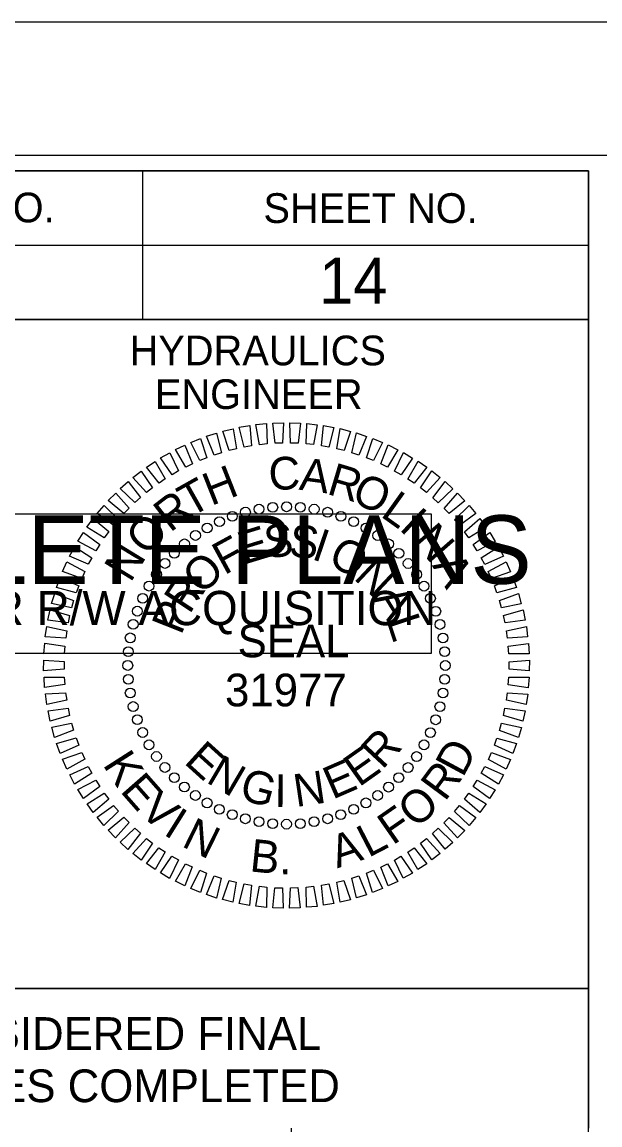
# Model space of a CAD drawing. Extents: x 557032 to 558930, y 525869 to 527437.
# Drawn here: x 558604.2 to 558701.3, y 526783.7 to 526969.2 of the extents above; entities that cross this region are included whole.
import ezdxf

# ---------------------------------------------------------------- set-up
doc = ezdxf.new("R2010")
doc.units = 0
for name, color, linetype in [('Default', 7, 'Continuous'), ('Sheet Cutting Line CELL', 7, 'Continuous'), ('Sheet Data Field CELL', 7, 'Continuous'), ('Sheet Plot Border Inside CELL', 7, 'Continuous'), ('Sheet Plot Border Outside CELL', 7, 'Continuous'), ('Sheet Profile CELL', 7, 'Continuous'), ('Sheet Profile Grid Major CELL', 7, 'Continuous'), ('Sheet Sticker Exception Certification CELL', 7, 'Continuous'), ('Sheet Sticker Incomplete CELL', 7, 'Continuous')]:
    doc.layers.add(name, color=color, linetype=linetype)

msp = doc.modelspace()

# ---------------------------------------------------------------- linework, layer by layer
at = {"layer": 'Default'}
for points in [[(558639, 526897.14), (558637.92, 526900.4), (558639.66, 526900.8), (558640.22, 526897.45)], [(558641.55, 526897.73), (558640.7, 526901.05), (558642.46, 526901.33), (558642.79, 526897.95)], [(558644.13, 526898.13), (558643.51, 526901.51), (558645.29, 526901.67), (558645.38, 526898.27)], [(558646.73, 526898.36), (558646.35, 526901.77), (558648.13, 526901.8), (558647.99, 526898.41)], [(558649.34, 526898.4), (558649.2, 526901.83), (558650.98, 526901.74), (558650.6, 526898.37)], [(558651.95, 526898.26), (558652.05, 526901.7), (558653.82, 526901.48), (558653.2, 526898.14)], [(558654.54, 526897.94), (558654.88, 526901.36), (558656.63, 526901.02), (558655.78, 526897.73)], [(558657.11, 526897.44), (558657.68, 526900.83), (558659.4, 526900.37), (558658.33, 526897.14)], [(558634.07, 526895.45), (558632.54, 526898.52), (558634.2, 526899.16), (558635.23, 526895.92)], [(558636.51, 526896.38), (558635.2, 526899.56), (558636.9, 526900.08), (558637.7, 526896.78)], [(558659.63, 526896.76), (558660.44, 526900.1), (558662.12, 526899.52), (558660.83, 526896.38)], [(558662.1, 526895.91), (558663.14, 526899.18), (558664.78, 526898.49), (558663.27, 526895.45)], [(558629.41, 526893.08), (558627.47, 526895.92), (558629.03, 526896.78), (558630.5, 526893.72)], [(558631.7, 526894.34), (558629.96, 526897.31), (558631.58, 526898.06), (558632.83, 526894.9)], [(558664.5, 526894.89), (558665.77, 526898.08), (558667.35, 526897.27), (558665.63, 526894.34)], [(558666.83, 526893.7), (558668.31, 526896.8), (558669.84, 526895.88), (558667.92, 526893.08)], [(558627.22, 526891.66), (558625.09, 526894.35), (558626.58, 526895.32), (558628.26, 526892.37)], [(558669.06, 526892.35), (558670.76, 526895.34), (558672.22, 526894.32), (558670.11, 526891.66)], [(558625.13, 526890.09), (558622.82, 526892.63), (558624.24, 526893.7), (558626.12, 526890.87)], [(558671.2, 526890.85), (558673.11, 526893.71), (558674.49, 526892.59), (558672.2, 526890.08)], [(558623.16, 526888.38), (558620.68, 526890.75), (558622.02, 526891.92), (558624.09, 526889.22)], [(558673.23, 526889.21), (558675.33, 526891.93), (558676.63, 526890.71), (558674.17, 526888.37)], [(558621.31, 526886.53), (558618.67, 526888.72), (558619.93, 526889.98), (558622.18, 526887.44)], [(558675.14, 526887.42), (558677.42, 526889.99), (558678.64, 526888.69), (558676.02, 526886.53)], [(558619.6, 526884.56), (558616.81, 526886.57), (558617.97, 526887.91), (558620.4, 526885.53)], [(558676.92, 526885.51), (558679.38, 526887.91), (558680.5, 526886.53), (558677.73, 526884.55)], [(558618.02, 526882.48), (558615.1, 526884.28), (558616.17, 526885.7), (558618.76, 526883.5)], [(558678.56, 526883.48), (558681.18, 526885.71), (558682.2, 526884.25), (558679.31, 526882.47)], [(558616.6, 526880.29), (558613.56, 526881.88), (558614.53, 526883.37), (558617.26, 526881.36)], [(558680.06, 526881.34), (558682.83, 526883.38), (558683.74, 526881.85), (558680.73, 526880.28)], [(558615.33, 526878.01), (558612.18, 526879.38), (558613.05, 526880.94), (558615.91, 526879.12)], [(558681.4, 526879.1), (558684.3, 526880.94), (558685.11, 526879.35), (558682, 526877.99)], [(558614.23, 526875.64), (558610.99, 526876.79), (558611.74, 526878.41), (558614.73, 526876.79)], [(558682.58, 526876.77), (558685.61, 526878.4), (558686.3, 526876.76), (558683.1, 526875.63)], [(558613.29, 526873.2), (558609.98, 526874.13), (558610.62, 526875.79), (558613.71, 526874.39)], [(558683.6, 526874.37), (558686.73, 526875.78), (558687.31, 526874.1), (558684.04, 526873.19)], [(558612.52, 526870.7), (558609.16, 526871.4), (558609.68, 526873.1), (558612.86, 526871.92)], [(558684.45, 526871.9), (558687.67, 526873.09), (558688.13, 526871.37), (558684.81, 526870.69)], [(558611.93, 526868.16), (558608.53, 526868.62), (558608.93, 526870.35), (558612.19, 526869.39)], [(558685.13, 526869.37), (558688.42, 526870.34), (558688.76, 526868.59), (558685.39, 526868.15)], [(558611.52, 526865.58), (558608.09, 526865.8), (558608.37, 526867.56), (558611.69, 526866.83)], [(558685.62, 526866.81), (558688.98, 526867.54), (558689.19, 526865.78), (558685.8, 526865.56)], [(558611.29, 526862.98), (558607.86, 526862.96), (558608.01, 526864.73), (558611.37, 526864.23)], [(558685.94, 526864.22), (558689.34, 526864.71), (558689.43, 526862.94), (558686.03, 526862.96)], [(558611.24, 526860.37), (558607.82, 526860.11), (558607.85, 526861.89), (558611.24, 526861.63)], [(558686.07, 526861.61), (558689.5, 526861.87), (558689.47, 526860.09), (558686.08, 526860.35)], [(558611.38, 526857.76), (558607.98, 526857.26), (558607.89, 526859.04), (558611.28, 526859.01)], [(558686.02, 526859), (558689.46, 526859.02), (558689.3, 526857.24), (558685.94, 526857.74)], [(558611.69, 526855.17), (558608.34, 526854.43), (558608.12, 526856.2), (558611.51, 526856.41)], [(558685.79, 526856.4), (558689.22, 526856.18), (558688.94, 526854.42), (558685.63, 526855.15)], [(558612.19, 526852.6), (558608.89, 526851.64), (558608.55, 526853.38), (558611.92, 526853.83)], [(558685.38, 526853.82), (558688.79, 526853.36), (558688.39, 526851.62), (558685.13, 526852.58)], [(558612.86, 526850.08), (558609.64, 526848.88), (558609.18, 526850.6), (558612.51, 526851.29)], [(558684.79, 526851.27), (558688.16, 526850.58), (558687.64, 526848.88), (558684.45, 526850.06)], [(558613.71, 526847.61), (558610.58, 526846.19), (558610, 526847.88), (558613.27, 526848.79)], [(558684.03, 526848.77), (558687.34, 526847.85), (558686.7, 526846.19), (558683.6, 526847.59)], [(558614.73, 526845.2), (558611.71, 526843.57), (558611.01, 526845.21), (558614.21, 526846.35)], [(558683.09, 526846.34), (558686.32, 526845.18), (558685.57, 526843.57), (558682.59, 526845.18)], [(558615.91, 526842.88), (558613.01, 526841.04), (558612.2, 526842.62), (558615.32, 526843.98)], [(558681.98, 526843.97), (558685.13, 526842.59), (558684.27, 526841.04), (558681.4, 526842.86)], [(558617.26, 526840.64), (558614.49, 526838.6), (558613.57, 526840.13), (558616.58, 526841.7)], [(558680.72, 526841.69), (558683.76, 526840.09), (558682.79, 526838.6), (558680.06, 526840.62)], [(558618.75, 526838.49), (558616.13, 526836.27), (558615.11, 526837.73), (558618.01, 526839.51)], [(558679.29, 526839.5), (558682.22, 526837.69), (558681.14, 526836.27), (558678.56, 526838.48)], [(558620.39, 526836.46), (558617.94, 526834.06), (558616.82, 526835.45), (558619.58, 526837.42)], [(558677.72, 526837.41), (558680.51, 526835.41), (558679.34, 526834.07), (558676.91, 526836.45)], [(558622.17, 526834.55), (558619.89, 526831.98), (558618.68, 526833.29), (558621.3, 526835.45)], [(558676, 526835.44), (558678.65, 526833.25), (558677.39, 526831.99), (558675.13, 526834.53)], [(558624.08, 526832.77), (558621.98, 526830.05), (558620.68, 526831.26), (558623.14, 526833.6)], [(558674.15, 526833.6), (558676.64, 526831.23), (558675.3, 526830.06), (558673.22, 526832.75)], [(558626.11, 526831.12), (558624.21, 526828.26), (558622.83, 526829.38), (558625.12, 526831.89)], [(558672.18, 526831.89), (558674.49, 526829.35), (558673.07, 526828.28), (558671.19, 526831.11)], [(558628.25, 526829.62), (558626.55, 526826.64), (558625.09, 526827.66), (558627.2, 526830.32)], [(558670.09, 526830.32), (558672.22, 526827.62), (558670.73, 526826.65), (558669.06, 526829.61)], [(558630.49, 526828.28), (558629, 526825.18), (558627.48, 526826.1), (558629.39, 526828.9)], [(558667.9, 526828.9), (558669.84, 526826.06), (558668.28, 526825.2), (558666.82, 526828.26)], [(558632.81, 526827.09), (558631.55, 526823.9), (558629.96, 526824.7), (558631.68, 526827.63)], [(558635.22, 526826.07), (558634.17, 526822.79), (558632.54, 526823.49), (558634.05, 526826.53)], [(558663.25, 526826.53), (558664.77, 526823.45), (558663.11, 526822.81), (558662.09, 526826.05)], [(558665.62, 526827.63), (558667.35, 526824.67), (558665.74, 526823.92), (558664.49, 526827.07)], [(558637.69, 526825.21), (558636.87, 526821.87), (558635.19, 526822.45), (558636.49, 526825.59)], [(558640.21, 526824.53), (558639.63, 526821.15), (558637.91, 526821.61), (558638.99, 526824.83)], [(558642.77, 526824.03), (558642.43, 526820.62), (558640.69, 526820.96), (558641.53, 526824.24)], [(558655.77, 526824.25), (558656.62, 526820.92), (558654.86, 526820.64), (558654.53, 526824.02)], [(558658.31, 526824.83), (558659.39, 526821.57), (558657.66, 526821.17), (558657.09, 526824.52)], [(558660.81, 526825.6), (558662.11, 526822.42), (558660.41, 526821.9), (558659.62, 526825.2)], [(558645.36, 526823.71), (558645.26, 526820.28), (558643.5, 526820.5), (558644.11, 526823.84)], [(558647.97, 526823.57), (558648.11, 526820.14), (558646.34, 526820.24), (558646.71, 526823.61)], [(558650.58, 526823.62), (558650.96, 526820.2), (558649.18, 526820.17), (558649.33, 526823.57)], [(558653.19, 526823.84), (558653.8, 526820.46), (558652.03, 526820.31), (558651.94, 526823.7)]]:
    msp.add_lwpolyline(points, close=True, dxfattribs=at)
for centre in [(558641.75, 526886.78), (558644.03, 526887.28), (558646.34, 526887.58), (558648.66, 526887.68), (558650.99, 526887.58), (558653.3, 526887.28), (558655.57, 526886.77), (558637.38, 526885.19), (558639.53, 526886.08), (558657.79, 526886.07), (558659.94, 526885.18), (558633.35, 526882.86), (558635.31, 526884.11), (558662.01, 526884.1), (558663.97, 526882.85), (558631.5, 526881.44), (558665.82, 526881.44), (558629.78, 526879.87), (558667.54, 526879.86), (558628.21, 526878.15), (558669.11, 526878.14), (558626.79, 526876.3), (558670.53, 526876.3), (558625.54, 526874.34), (558671.78, 526874.33), (558624.46, 526872.27), (558672.85, 526872.27), (558623.57, 526870.12), (558673.75, 526870.11), (558622.87, 526867.9), (558674.45, 526867.89), (558622.37, 526865.63), (558674.95, 526865.62), (558622.06, 526863.32), (558675.25, 526863.31), (558621.96, 526860.99), (558675.35, 526860.98), (558622.06, 526858.67), (558675.25, 526858.66), (558622.37, 526856.36), (558674.95, 526856.35), (558622.87, 526854.08), (558674.44, 526854.07), (558623.57, 526851.86), (558673.74, 526851.85), (558624.46, 526849.71), (558672.85, 526849.7), (558625.54, 526847.64), (558671.77, 526847.64), (558626.79, 526845.68), (558670.52, 526845.67), (558628.2, 526843.83), (558669.1, 526843.82), (558629.78, 526842.11), (558667.53, 526842.11), (558631.49, 526840.54), (558665.81, 526840.53), (558633.34, 526839.12), (558663.97, 526839.12), (558635.3, 526837.87), (558637.37, 526836.8), (558659.93, 526836.79), (558662, 526837.87), (558639.52, 526835.9), (558641.74, 526835.2), (558644.02, 526834.7), (558653.29, 526834.7), (558655.56, 526835.2), (558657.78, 526835.9), (558646.33, 526834.39), (558648.65, 526834.29), (558650.98, 526834.39)]:
    msp.add_circle(centre, 0.826, dxfattribs=at)
at = {"layer": 'Sheet Cutting Line CELL'}
msp.add_line((558716.45, 526969.22), (557032.45, 526969.22), dxfattribs=at)
at = {"layer": 'Sheet Plot Border Inside CELL'}
msp.add_lwpolyline([(557045.45, 525891.67), (558711.95, 525891.67), (558711.95, 526946.77), (557045.45, 526946.77)], close=True, dxfattribs=at)
at = {"layer": 'Sheet Plot Border Outside CELL'}
msp.add_lwpolyline([(557032.45, 525869.22), (558716.45, 525869.22), (558716.45, 526969.22), (557032.45, 526969.22)], close=True, dxfattribs=at)
at = {"layer": 'Sheet Profile CELL'}
for p, q in [((558624.45, 526944.17), (558624.45, 526919.17)), ((558499.4, 526931.67), (558699.45, 526931.67))]:
    msp.add_line(p, q, dxfattribs=at)
for points in [[(558699.45, 526944.22), (557199.45, 526944.22), (557199.45, 525894.22), (558699.45, 525894.22)], [(558499.4, 526944.22), (558699.45, 526944.22), (558699.45, 526919.17), (558499.4, 526919.17)], [(558599.45, 526919.17), (558699.45, 526919.17), (558699.45, 526806.67), (558599.45, 526806.67)]]:
    msp.add_lwpolyline(points, close=True, dxfattribs=at)
at = {"layer": 'Sheet Profile Grid Major CELL'}
msp.add_lwpolyline([(558649.45, 526783.17), (558649.45, 526444.22), (558699.45, 526444.22), (558699.45, 526794.22)], dxfattribs=at)
at = {"layer": 'Sheet Sticker Exception Certification CELL'}
for p, q in [((558499.4, 526806.67), (558699.44, 526806.67)), ((558499.4, 526806.67), (558699.44, 526806.67)), ((558699.44, 526806.66), (558699.44, 526783.16)), ((558699.44, 526806.66), (558699.44, 526783.16))]:
    msp.add_line(p, q, dxfattribs=at)
at = {"layer": 'Sheet Sticker Incomplete CELL'}
msp.add_lwpolyline([(558525.97, 526863.02), (558525.97, 526886.52), (558672.97, 526886.52), (558672.97, 526863.02)], close=True, dxfattribs=at)

# ---------------------------------------------------------------- texts
at = {"layer": 'Default'}
for s, height, rotation, p in [('C', 5.5, 1.9509, (558645.72, 526890.49)), ('A', 5.5, 352.4458, (558650.64, 526890.57)), ('R', 5.5, 343.3983, (558655.26, 526889.89)), ('H', 5.5, 21.5901, (558635.98, 526887.79)), ('O', 5.5, 335.1897, (558659.32, 526888.65)), ('T', 5.5, 29.3793, (558632.46, 526885.82)), ('R', 5.5, 37.5879, (558629.08, 526883.26)), ('L', 5.5, 324.4645, (558664.29, 526886.18)), ('I', 5.5, 316.9994, (558667.43, 526883.94)), ('O', 5.5, 48.3131, (558625.28, 526879.23)), ('E', 5.5, 16.975, (558641.47, 526877.93)), ('S', 5.5, 5.2127, (558645.08, 526879.04)), ('S', 5.5, 353.2538, (558648.89, 526879.39)), ('I', 5.5, 341.2948, (558652.7, 526878.94)), ('N', 5.5, 311.0594, (558669.7, 526881.87)), ('F', 5.5, 28.6529, (558638.19, 526876.12)), ('O', 5.5, 332.5394, (558655.39, 526878.12)), ('N', 5.5, 58.5235, (558622.42, 526874.79)), ('O', 5.5, 44.4617, (558634.46, 526872.7)), ('N', 5.5, 316.7306, (558659.8, 526875.63)), ('A', 5.5, 300.849, (558673.07, 526877.81)), ('R', 5.5, 56.5612, (558632.32, 526869.47)), ('A', 5.5, 301.6806, (558663.22, 526872.24)), ('P', 5.5, 68.3234, (558630.94, 526865.96)), ('L', 5.5, 288.3447, (558665.42, 526868.58)), ('SEAL', 5.504, 359.989, (558640.43, 526862.37)), ('31977', 5.504, 359.989, (558638.31, 526854.11)), ('R', 5.5, 47.032, (558664.76, 526843.35)), ('K', 5.5, 302.6028, (558617.66, 526844.33)), ('E', 5.5, 317.8396, (558631.25, 526844.63)), ('E', 5.5, 35.2697, (558660.83, 526840.44)), ('D', 5.5, 61.6895, (558678.29, 526842)), ('N', 5.5, 329.6019, (558634.95, 526841.43)), ('E', 5.5, 23.5075, (558656.39, 526838.39)), ('E', 5.5, 311.3071, (558620.54, 526839.83)), ('G', 5.5, 344.6519, (558640.5, 526838.54)), ('N', 5.5, 8.4574, (558650.25, 526837.16)), ('R', 5.5, 53.4809, (558675.27, 526837.96)), ('I', 5.5, 359.702, (558646.61, 526837.19)), ('V', 5.5, 319.287, (558623.75, 526836.13)), ('O', 5.5, 42.7557, (558670.52, 526833.41)), ('F', 5.5, 34.833, (558666.51, 526830.66)), ('I', 5.5, 327.9723, (558627.79, 526832.65)), ('N', 5.5, 333.9122, (558630.83, 526830.64)), ('L', 5.5, 27.3679, (558662.42, 526828.6)), ('B', 5.5, 354.009, (558642.34, 526826.37)), ('A', 5.5, 18.3204, (558657.16, 526826.84)), ('.', 5.5, 2.3511, (558647.43, 526825.82))]:
    msp.add_text(s, height=height, rotation=rotation, dxfattribs=at).set_placement(p)
at = {"layer": 'Sheet Data Field CELL'}
msp.add_text('14 ', height=7.75, dxfattribs=at).set_placement((558654.12, 526921.83))
at = {"layer": 'Sheet Profile CELL'}
for s, height, p in [('PROJECT REFERENCE NO.', 5.0001, (558521.62, 526935.53)), ('SHEET NO.', 5, (558644.77, 526935.43)), ('HYDRAULICS', 5, (558622.27, 526911.48)), ('ENGINEER', 5, (558626.52, 526904.13))]:
    msp.add_text(s, height=height, dxfattribs=at).set_placement(p)
at = {"layer": 'Sheet Sticker Exception Certification CELL'}
for s, p in [('DOCUMENT NOT CONSIDERED FINAL', (558520.47, 526796.33)), ('DOCUMENT NOT CONSIDERED FINAL', (558520.47, 526796.33)), ('UNLESS ALL SIGNATURES COMPLETED', (558515.4, 526787.53)), ('UNLESS ALL SIGNATURES COMPLETED', (558515.4, 526787.53))]:
    msp.add_text(s, height=5.5, dxfattribs=at).set_placement(p)
at = {"layer": 'Sheet Sticker Incomplete CELL'}
for s, height, p in [('INCOMPLETE PLANS', 11.52, (558534.92, 526874.72)), ('DO NOT USE FOR R/W ACQUISITION', 5.76, (558538.17, 526867.77))]:
    msp.add_text(s, height=height, dxfattribs=at).set_placement(p)

doc.saveas('drawing.dxf')
